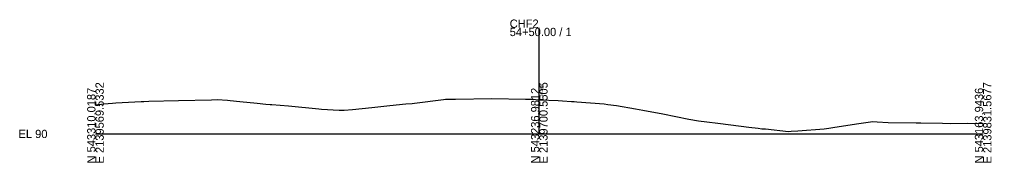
# Model space of a CAD drawing. Extents: x -12831 to 2303, y -10 to 39065.
# Drawn here: x 1974.3 to 2302.8, y 8990.3 to 9038.7 of the extents above; entities that cross this region are included whole.
import ezdxf

# ---------------------------------------------------------------- set-up
doc = ezdxf.new("R2010")
doc.units = 0
for name, color, linetype in [('RD_GPK_XS_Cell', 7, 'Continuous'), ('RD_XS_ExGround', 7, 'Continuous'), ('RD_XS_TX_Elev_EX', 7, 'Continuous')]:
    doc.layers.add(name, color=color, linetype=linetype)

msp = doc.modelspace()

# ---------------------------------------------------------------- linework, layer by layer
at = {"layer": 'RD_GPK_XS_Cell'}
for p, q in [((2150, 9000), (2150, 9035.89)), ((2000, 9000), (2150, 9000)), ((2150, 9000), (2300, 9000))]:
    msp.add_line(p, q, dxfattribs=at)
at = {"layer": 'RD_XS_ExGround'}
for p, q in [((2117.58, 9011.62), (2118.28, 9011.7)), ((2118.28, 9011.7), (2120.83, 9011.78)), ((2120.83, 9011.78), (2121.7, 9011.79)), ((2121.7, 9011.79), (2133.95, 9011.96)), ((2133.95, 9011.96), (2145.35, 9011.76)), ((2145.35, 9011.76), (2146.81, 9011.74)), ((2146.81, 9011.74), (2147.5, 9011.7)), ((2147.5, 9011.7), (2150, 9011.58)), ((2000, 9009.85), (2000.82, 9009.95)), ((2000.82, 9009.95), (2002.03, 9010.08)), ((2002.03, 9010.08), (2002.83, 9010.16)), ((2002.83, 9010.16), (2005.8, 9010.42)), ((2005.8, 9010.42), (2006.83, 9010.49)), ((2006.83, 9010.49), (2015.49, 9010.97)), ((2015.49, 9010.97), (2016.33, 9011.02)), ((2016.33, 9011.02), (2018.02, 9011.06)), ((2018.02, 9011.06), (2028.05, 9011.28)), ((2028.05, 9011.28), (2039.21, 9011.56)), ((2039.21, 9011.56), (2041.16, 9011.6)), ((2041.16, 9011.6), (2044.6, 9011.42)), ((2044.6, 9011.42), (2045.51, 9011.33)), ((2045.51, 9011.33), (2048.8, 9010.98)), ((2048.8, 9010.98), (2054.65, 9010.38)), ((2054.65, 9010.38), (2057.58, 9010.11)), ((2057.58, 9010.11), (2059.02, 9009.98)), ((2059.02, 9009.98), (2059.62, 9009.93)), ((2059.62, 9009.93), (2065.19, 9009.55)), ((2065.19, 9009.55), (2075.48, 9008.48)), ((2075.48, 9008.48), (2076.37, 9008.4)), ((2076.37, 9008.4), (2082.34, 9007.99)), ((2086.86, 9008.25), (2093.36, 9008.95)), ((2093.36, 9008.95), (2097.42, 9009.37)), ((2097.42, 9009.37), (2099.5, 9009.6)), ((2099.5, 9009.6), (2104.92, 9010.16)), ((2104.92, 9010.16), (2107.02, 9010.31)), ((2107.02, 9010.31), (2107.82, 9010.4)), ((2107.82, 9010.4), (2117.58, 9011.62)), ((2150, 9011.58), (2156.35, 9011.26)), ((2156.35, 9011.26), (2157.84, 9011.18)), ((2157.84, 9011.18), (2160.83, 9011.02)), ((2160.83, 9011.02), (2161.79, 9010.97)), ((2161.79, 9010.97), (2162.66, 9010.89)), ((2162.66, 9010.89), (2171.92, 9010.12)), ((2171.92, 9010.12), (2173.21, 9009.99)), ((2173.21, 9009.99), (2176.12, 9009.56)), ((2176.12, 9009.56), (2182.5, 9008.51)), ((2182.5, 9008.51), (2185.04, 9008.01)), ((2082.34, 9007.99), (2084.07, 9008.06)), ((2084.07, 9008.06), (2086.86, 9008.25)), ((2185.04, 9008.01), (2191.72, 9006.74)), ((2191.72, 9006.74), (2200.56, 9005)), ((2200.56, 9005), (2203.81, 9004.42)), ((2203.81, 9004.42), (2206.64, 9004.14)), ((2206.64, 9004.14), (2210.29, 9003.69)), ((2210.29, 9003.69), (2214.7, 9003.06)), ((2214.7, 9003.06), (2220.78, 9002.33)), ((2220.78, 9002.33), (2223.99, 9001.95)), ((2223.99, 9001.95), (2225.25, 9001.77)), ((2246.28, 9001.77), (2247.79, 9001.98)), ((2247.79, 9001.98), (2249.84, 9002.29)), ((2249.84, 9002.29), (2257.97, 9003.57)), ((2257.97, 9003.57), (2262.66, 9004.2)), ((2262.66, 9004.2), (2264.23, 9004.06)), ((2264.23, 9004.06), (2267.92, 9003.87)), ((2267.92, 9003.87), (2277.37, 9003.75)), ((2277.37, 9003.75), (2278.17, 9003.73)), ((2278.17, 9003.73), (2278.91, 9003.73)), ((2278.91, 9003.73), (2286.28, 9003.6)), ((2286.28, 9003.6), (2289.01, 9003.51)), ((2289.01, 9003.51), (2294.64, 9003.6)), ((2294.64, 9003.6), (2300, 9003.51)), ((2225.25, 9001.77), (2226.47, 9001.69)), ((2226.47, 9001.69), (2234.24, 9000.85)), ((2234.24, 9000.85), (2235.14, 9000.88)), ((2235.14, 9000.88), (2237.37, 9001.09)), ((2237.37, 9001.09), (2246.28, 9001.77))]:
    msp.add_line(p, q, dxfattribs=at)

# ---------------------------------------------------------------- texts
at = {"layer": 'RD_GPK_XS_Cell'}
for s, p in [('CHF2', (2140, 9035.89)), ('54+50.00 / 1', (2140, 9033.09)), ('EL 90', (1974, 8998.6))]:
    msp.add_text(s, height=2.8, dxfattribs=at).set_placement(p)
for s, p in [('N 543310.0187', (2000, 8990)), ('E 2139569.5332', (2002.8, 8990)), ('N 543236.9812', (2150, 8990)), ('E 2139700.5505', (2152.8, 8990)), ('N 543163.9436', (2300, 8990)), ('E 2139831.5677', (2302.8, 8990))]:
    msp.add_text(s, height=2.8, rotation=90, dxfattribs=at).set_placement(p)
at = {"layer": 'RD_XS_TX_Elev_EX'}
msp.add_text('101.58', height=1, rotation=90, dxfattribs=at).set_placement((2151.25, 9012.58))

doc.saveas('drawing.dxf')
